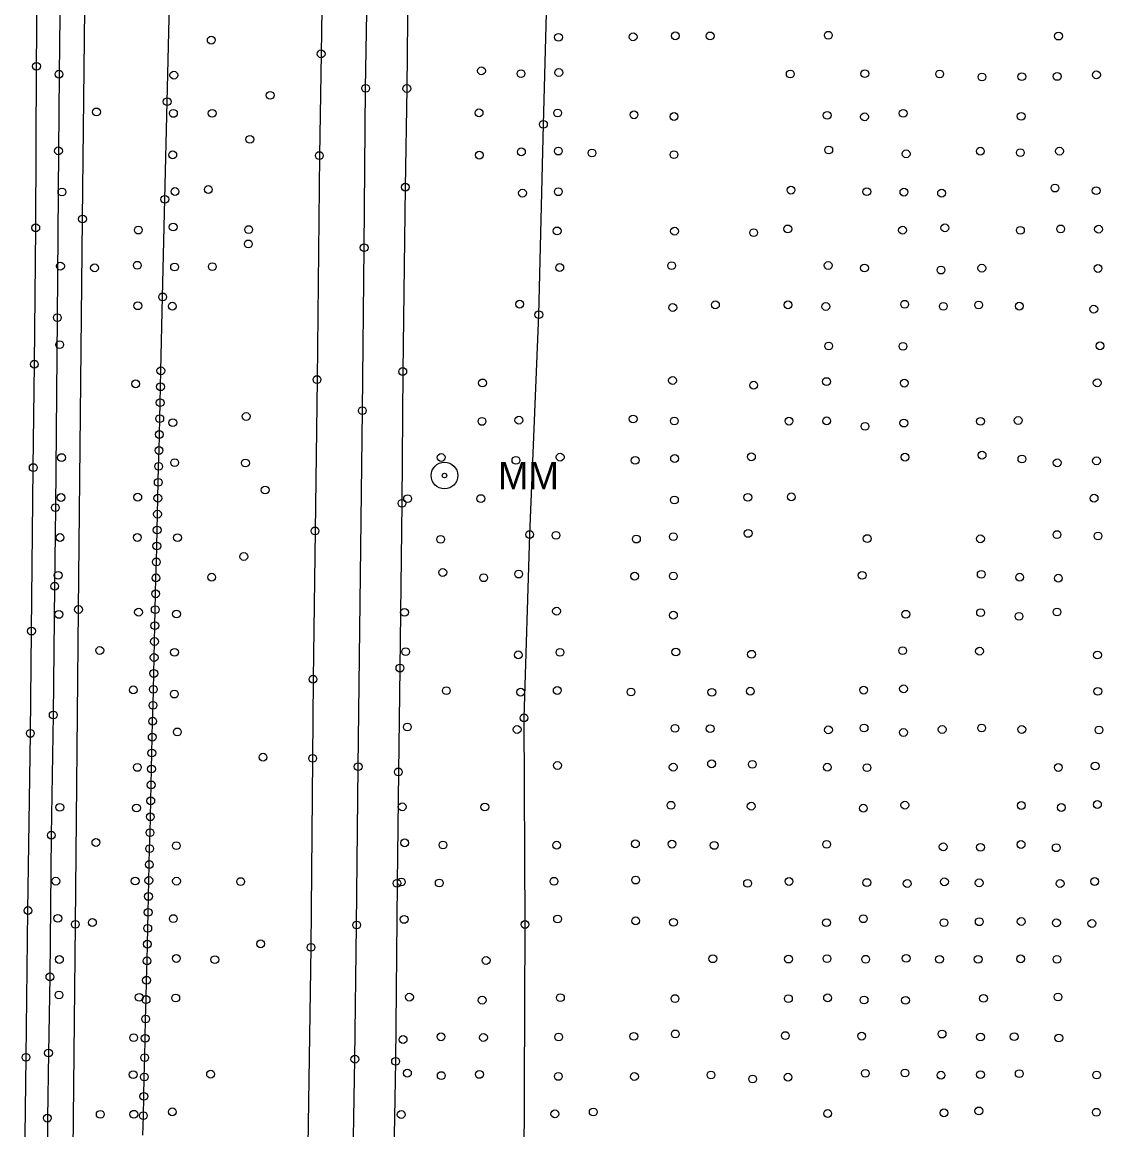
# Model space of a CAD drawing. Extents: x 20503438 to 20508873, y 7964251 to 7984667.
# Drawn here: x 20506609.5 to 20506886.4, y 7967934.6 to 7968218.3 of the extents above; entities that cross this region are included whole.
import ezdxf

# ---------------------------------------------------------------- set-up
doc = ezdxf.new("R2010")
doc.units = 0
for name, color, linetype in [('SurBreakLine', 7, 'Continuous'), ('SurConcreteSlab', 7, 'Continuous'), ('SurDrainageArrowDown', 7, 'Continuous'), ('SurDrainageArrowUp', 7, 'Continuous'), ('SurEdgeRoadPaved', 7, 'Continuous'), ('SurEdgeShoulderPaved', 7, 'Continuous'), ('SurGuardRailCable', 7, 'Continuous'), ('SurPointsNonDTM', 7, 'Continuous'), ('SurRoadPoints', 7, 'Continuous'), ('SurSurveyPoints', 7, 'Continuous')]:
    doc.layers.add(name, color=color, linetype=linetype)

msp = doc.modelspace()

# ---------------------------------------------------------------- linework, layer by layer
at = {"layer": 'SurBreakLine'}
msp.add_lwpolyline([(20506690.26, 7968518.48), (20506689.75, 7968484.33), (20506689.14, 7968441.26), (20506688.76, 7968414.99), (20506687.98, 7968360.62), (20506687.56, 7968335.59), (20506687.22, 7968303.54), (20506686.72, 7968264.08), (20506686.24, 7968221.64), (20506686.02, 7968210.16), (20506685.58, 7968184.12), (20506684.98, 7968126.76), (20506684.47, 7968088.01), (20506683.95, 7968050.04), (20506683.85, 7968029.76), (20506683.42, 7967981.38), (20506682.3, 7967907.93)], dxfattribs=at)
at = {"layer": 'SurConcreteSlab'}
msp.add_lwpolyline([(20506712.33, 7968509.69), (20506711.9, 7968484.13), (20506711.28, 7968449.91), (20506710.98, 7968435.8), (20506710.8, 7968427.34), (20506710.57, 7968413.18), (20506710.2, 7968376.16), (20506709.68, 7968335.8), (20506709.4, 7968315.24), (20506709.29, 7968306.55), (20506709.24, 7968300.91), (20506708.97, 7968272.73), (20506708.28, 7968236.62), (20506707.97, 7968201.29), (20506707.58, 7968176.03), (20506706.92, 7968128.82), (20506706.72, 7968095.09), (20506706.2, 7968052.89), (20506705.8, 7968026.3), (20506705.46, 7967997.77), (20506705.09, 7967952.19), (20506704.42, 7967914.18)], dxfattribs=at)
at = {"layer": 'SurDrainageArrowDown'}
msp.add_lwpolyline([(20506640.39, 7967933.31), (20506640.5, 7967938.27), (20506640.62, 7967943.22), (20506640.74, 7967948.18), (20506640.85, 7967953.13), (20506640.97, 7967958.09), (20506641.09, 7967963.04), (20506641.2, 7967968), (20506641.32, 7967972.95), (20506641.44, 7967977.91), (20506641.54, 7967982.19), (20506641.63, 7967986.26), (20506641.73, 7967990.34), (20506641.82, 7967994.42), (20506641.92, 7967998.5), (20506642.02, 7968002.58), (20506642.11, 7968006.66), (20506642.21, 7968010.73), (20506642.3, 7968014.81), (20506642.4, 7968018.89), (20506642.5, 7968022.97), (20506642.59, 7968027.05), (20506642.69, 7968031.13), (20506642.78, 7968035.21), (20506642.88, 7968039.28), (20506642.98, 7968043.36), (20506643.07, 7968047.44), (20506643.17, 7968051.52), (20506643.26, 7968055.6), (20506643.36, 7968059.68), (20506643.46, 7968063.76), (20506643.55, 7968067.83), (20506643.65, 7968071.91), (20506643.74, 7968075.99), (20506643.84, 7968080.07), (20506643.94, 7968084.15), (20506644.03, 7968088.23), (20506644.13, 7968092.3), (20506644.22, 7968096.38), (20506644.32, 7968100.46), (20506644.42, 7968104.54), (20506644.51, 7968108.62), (20506644.61, 7968112.7), (20506644.7, 7968116.77), (20506644.8, 7968120.85), (20506644.9, 7968124.93), (20506644.99, 7968129.01), (20506645.44, 7968147.93), (20506646.02, 7968172.92), (20506646.61, 7968197.92), (20506647.2, 7968222.91)], dxfattribs=at)
at = {"layer": 'SurDrainageArrowUp'}
msp.add_lwpolyline([(20506738, 7967924.5), (20506738.23, 7967987.24), (20506737.97, 7968040.14), (20506739.42, 7968087.08), (20506741.75, 7968143.37), (20506742.94, 7968192.11), (20506744.24, 7968239.72), (20506747.37, 7968292.34), (20506747.64, 7968338.63), (20506748.32, 7968361.98), (20506749.44, 7968389.93), (20506749.76, 7968438.94), (20506751.33, 7968487.3), (20506751.06, 7968489.97)], dxfattribs=at)
at = {"layer": 'SurEdgeRoadPaved'}
for points in [[(20506610.04, 7967919.68), (20506610.47, 7967953.23), (20506610.95, 7967990.8), (20506611.57, 7968036.16), (20506611.86, 7968062.36), (20506612.31, 7968104.23), (20506612.6, 7968130.7), (20506612.95, 7968165.62), (20506613.14, 7968206.99), (20506613.43, 7968233.98), (20506614.06, 7968276.04), (20506614.62, 7968307.91), (20506615.76, 7968378.52), (20506616.8, 7968454.85), (20506618.19, 7968552.78)], [(20506686.56, 7967334.59), (20506686.95, 7967373.78), (20506689.55, 7967556.46), (20506690.33, 7967629.33), (20506692, 7967750.22), (20506692.37, 7967781.34), (20506692.82, 7967818.08), (20506693.38, 7967854.94), (20506693.74, 7967887.88), (20506694.06, 7967917.79), (20506694.67, 7967952.73), (20506695.11, 7967987.1), (20506695.52, 7968027.63), (20506696.58, 7968118.81), (20506697.03, 7968160.54), (20506697.41, 7968201.34), (20506698.01, 7968235.32), (20506698.41, 7968270.98), (20506698.89, 7968306.65), (20506699.7, 7968354.59), (20506700.7, 7968438.24), (20506701.3, 7968479.04), (20506702.09, 7968524.73)]]:
    msp.add_lwpolyline(points, dxfattribs=at)
at = {"layer": 'SurEdgeShoulderPaved'}
msp.add_lwpolyline([(20506624.07, 7968571.84), (20506622.9, 7968477.89), (20506622.6, 7968440.86), (20506622.03, 7968407.41), (20506621.73, 7968387.9), (20506620.89, 7968340.34), (20506620.58, 7968323), (20506620.12, 7968296.25), (20506619.36, 7968242.53), (20506618.92, 7968204.96), (20506618.76, 7968185.33), (20506618.47, 7968142.62), (20506617.98, 7968093.95), (20506617.79, 7968073.85), (20506617.43, 7968040.86), (20506616.93, 7968010.09), (20506616.58, 7967973.81), (20506616.23, 7967954.34), (20506615.93, 7967937.65), (20506615.89, 7967920.93)], dxfattribs=at)
at = {"layer": 'SurGuardRailCable'}
msp.add_lwpolyline([(20506615.02, 7967359.71), (20506615.99, 7967430.36), (20506617.34, 7967530.35), (20506618.65, 7967630.34), (20506619.88, 7967727.43), (20506620.83, 7967791.42), (20506621.77, 7967855.41), (20506622.47, 7967921.12), (20506623.1, 7967987.28), (20506623.9, 7968067.87), (20506624.93, 7968167.87), (20506626.04, 7968267.86), (20506627.42, 7968367.85), (20506628.76, 7968467.84), (20506630.09, 7968567.83)], dxfattribs=at)
at = {"layer": 'SurPointsNonDTM'}
for centre in [(20506624.93, 7968167.87), (20506623.9, 7968067.87), (20506623.1, 7967987.28)]:
    msp.add_circle(centre, 1, dxfattribs=at)
at = {"layer": 'SurRoadPoints'}
for radius in [3.43, 0.571]:
    msp.add_circle((20506717.61, 7968102.19), radius, dxfattribs=at)
at = {"layer": 'SurSurveyPoints'}
for centre in [(20506657.89, 7968213.69), (20506746.81, 7968214.41), (20506765.91, 7968214.51), (20506776.71, 7968214.78), (20506785.62, 7968214.76), (20506815.89, 7968214.93), (20506874.83, 7968214.72), (20506686.02, 7968210.16), (20506613.14, 7968206.99), (20506618.92, 7968204.96), (20506648.32, 7968204.71), (20506727.08, 7968205.82), (20506737.21, 7968205.11), (20506746.89, 7968205.38), (20506806.14, 7968205), (20506825.23, 7968205.08), (20506844.39, 7968205.02), (20506855.23, 7968204.24), (20506865.43, 7968204.32), (20506874.49, 7968204.39), (20506884.55, 7968204.78), (20506697.41, 7968201.34), (20506707.97, 7968201.29), (20506672.96, 7968199.55), (20506646.61, 7968197.92), (20506628.5, 7968195.3), (20506648.2, 7968194.92), (20506658.12, 7968194.95), (20506726.47, 7968195.06), (20506746.58, 7968195.04), (20506766.15, 7968194.57), (20506776.38, 7968194.13), (20506815.61, 7968194.43), (20506825.17, 7968194.04), (20506835.07, 7968194.94), (20506865.28, 7968194.18), (20506742.94, 7968192.11), (20506667.78, 7968188.28), (20506618.76, 7968185.33), (20506648.03, 7968184.3), (20506726.54, 7968184.23), (20506737.31, 7968185.07), (20506746.77, 7968185.27), (20506755.38, 7968184.77), (20506776.37, 7968184.37), (20506816, 7968185.55), (20506835.82, 7968184.57), (20506854.83, 7968185.24), (20506865.05, 7968184.88), (20506875.08, 7968185.25), (20506685.58, 7968184.12), (20506707.58, 7968176.03), (20506873.93, 7968175.8), (20506619.65, 7968174.8), (20506646.02, 7968172.92), (20506648.6, 7968174.91), (20506657.15, 7968175.42), (20506737.58, 7968174.51), (20506746.76, 7968174.86), (20506806.33, 7968175.27), (20506825.75, 7968174.89), (20506835.25, 7968174.77), (20506844.89, 7968174.5), (20506884.46, 7968175.13), (20506612.95, 7968165.62), (20506639.23, 7968165.04), (20506648.15, 7968165.83), (20506667.46, 7968165.17), (20506746.45, 7968164.83), (20506776.52, 7968164.76), (20506796.78, 7968164.38), (20506805.51, 7968165.34), (20506834.89, 7968165.01), (20506845.73, 7968165.61), (20506865.08, 7968164.99), (20506875.39, 7968165.34), (20506885.08, 7968165.27), (20506667.4, 7968161.5), (20506697.03, 7968160.54), (20506638.97, 7968156.04), (20506775.78, 7968155.92), (20506815.85, 7968155.99), (20506619.28, 7968155.8), (20506628, 7968155.37), (20506648.5, 7968155.59), (20506658.16, 7968155.68), (20506747.12, 7968155.45), (20506825.14, 7968155.35), (20506844.75, 7968154.8), (20506855.2, 7968155.29), (20506884.93, 7968155.22), (20506645.44, 7968147.93), (20506639.09, 7968145.67), (20506647.93, 7968145.55), (20506736.85, 7968146.07), (20506776.06, 7968145.21), (20506786.98, 7968145.89), (20506805.57, 7968145.9), (20506815.25, 7968145.47), (20506835.43, 7968146.05), (20506845.34, 7968145.51), (20506854.38, 7968145.87), (20506864.81, 7968145.56), (20506883.86, 7968144.81), (20506618.47, 7968142.62), (20506741.75, 7968143.37), (20506619.08, 7968135.71), (20506815.97, 7968135.37), (20506835.02, 7968135.28), (20506885.44, 7968135.4), (20506612.6, 7968130.7), (20506644.99, 7968129.01), (20506706.92, 7968128.82), (20506638.53, 7968125.67), (20506644.9, 7968124.93), (20506684.98, 7968126.76), (20506727.36, 7968125.91), (20506776.01, 7968126.53), (20506796.79, 7968125.32), (20506815.42, 7968126.25), (20506835.34, 7968125.86), (20506884.74, 7968125.92), (20506644.8, 7968120.85), (20506644.7, 7968116.77), (20506666.83, 7968117.32), (20506696.58, 7968118.81), (20506736.66, 7968116.36), (20506765.91, 7968116.67), (20506776.47, 7968116.14), (20506805.82, 7968116.13), (20506815.48, 7968116.19), (20506864.5, 7968116.29), (20506648.05, 7968115.74), (20506727.22, 7968116.05), (20506825.3, 7968114.79), (20506835.24, 7968115.62), (20506854.87, 7968116.06), (20506644.61, 7968112.7), (20506644.51, 7968108.62), (20506619.56, 7968106.79), (20506648.52, 7968105.49), (20506666.64, 7968105.4), (20506716.77, 7968106.82), (20506735.9, 7968106.08), (20506747.22, 7968106.9), (20506766.43, 7968106.08), (20506776.53, 7968106.55), (20506796.2, 7968106.99), (20506835.54, 7968106.9), (20506855.26, 7968107.41), (20506865.46, 7968106.42), (20506874.5, 7968105.45), (20506884.56, 7968105.95), (20506612.31, 7968104.23), (20506644.42, 7968104.54), (20506644.32, 7968100.46), (20506619.4, 7968096.57), (20506639.07, 7968096.65), (20506644.22, 7968096.38), (20506671.69, 7968098.49), (20506708.16, 7968096.28), (20506726.92, 7968096.29), (20506795.29, 7968096.6), (20506806.41, 7968096.72), (20506883.94, 7968096.39), (20506617.98, 7968093.95), (20506706.72, 7968095.09), (20506776.48, 7968095.92), (20506644.13, 7968092.3), (20506644.03, 7968088.23), (20506684.47, 7968088.01), (20506619.15, 7968086.31), (20506638.97, 7968086.34), (20506649.25, 7968086.29), (20506716.63, 7968085.87), (20506739.42, 7968087.08), (20506746.16, 7968086.88), (20506766.75, 7968085.92), (20506776.19, 7968086.54), (20506795.36, 7968087.37), (20506825.85, 7968086.05), (20506854.84, 7968086), (20506874.43, 7968087.07), (20506884.96, 7968086.71), (20506643.94, 7968084.15), (20506643.84, 7968080.07), (20506666.23, 7968081.45), (20506618.7, 7968076.65), (20506717.18, 7968077.38), (20506736.59, 7968076.96), (20506766.3, 7968076.42), (20506776.22, 7968076.45), (20506824.54, 7968076.62), (20506855.05, 7968076.9), (20506617.79, 7968073.85), (20506643.74, 7968075.99), (20506658, 7968076.15), (20506727.65, 7968076.02), (20506864.88, 7968076.15), (20506874.77, 7968075.9), (20506643.65, 7968071.91), (20506618.87, 7968066.63), (20506639.27, 7968067.2), (20506643.55, 7968067.83), (20506648.98, 7968066.72), (20506707.37, 7968067.15), (20506746.3, 7968067.46), (20506776.23, 7968066.43), (20506835.74, 7968066.67), (20506854.88, 7968067.07), (20506864.71, 7968066.15), (20506874.46, 7968067.26), (20506611.86, 7968062.36), (20506643.46, 7968063.76), (20506643.36, 7968059.68), (20506629.35, 7968057.4), (20506648.49, 7968056.93), (20506707.67, 7968057.1), (20506747.17, 7968056.92), (20506776.85, 7968056.99), (20506834.94, 7968057.33), (20506854.61, 7968057.21), (20506643.26, 7968055.6), (20506736.51, 7968056.27), (20506796.23, 7968056.43), (20506884.8, 7968056.22), (20506643.17, 7968051.52), (20506706.2, 7968052.89), (20506683.95, 7968050.04), (20506637.95, 7968047.31), (20506643.07, 7968047.44), (20506648.42, 7968046.23), (20506718.08, 7968047.12), (20506737.12, 7968046.72), (20506746.48, 7968047.16), (20506765.35, 7968046.77), (20506786.08, 7968046.69), (20506795.93, 7968046.97), (20506824.95, 7968047.24), (20506835.15, 7968047.58), (20506884.89, 7968046.95), (20506642.98, 7968043.36), (20506617.43, 7968040.86), (20506737.97, 7968040.14), (20506642.88, 7968039.28), (20506708.08, 7968037.8), (20506736.21, 7968037.16), (20506776.64, 7968037.45), (20506785.63, 7968037.39), (20506815.93, 7968037.07), (20506825.05, 7968037.56), (20506845.04, 7968037.16), (20506855.15, 7968037.54), (20506865.43, 7968037.17), (20506885.21, 7968037.04), (20506611.57, 7968036.16), (20506642.78, 7968035.21), (20506649.19, 7968036.54), (20506835.14, 7968036.4), (20506642.69, 7968031.13), (20506671.15, 7968030.07), (20506683.85, 7968029.76), (20506786, 7968028.37), (20506796.45, 7968028.25), (20506638.96, 7968027.45), (20506642.59, 7968027.05), (20506695.52, 7968027.63), (20506705.8, 7968026.3), (20506746.55, 7968027.96), (20506776.17, 7968027.52), (20506815.64, 7968027.51), (20506825.81, 7968027.4), (20506874.77, 7968027.44), (20506884.21, 7968027.8), (20506642.5, 7968022.97), (20506619.1, 7968017.22), (20506638.75, 7968017.06), (20506642.4, 7968018.89), (20506706.79, 7968017.36), (20506727.94, 7968017.33), (20506775.61, 7968017.76), (20506796.15, 7968017.52), (20506824.86, 7968017.01), (20506835.5, 7968017.78), (20506865.32, 7968017.7), (20506875.56, 7968017.19), (20506884.79, 7968017.96), (20506642.3, 7968014.81), (20506616.93, 7968010.09), (20506642.21, 7968010.73), (20506628.36, 7968008.24), (20506642.11, 7968006.66), (20506648.95, 7968007.4), (20506707.43, 7968008.14), (20506717.22, 7968007.6), (20506746.34, 7968007.53), (20506766.5, 7968007.88), (20506775.85, 7968007.81), (20506786.67, 7968007.48), (20506815.46, 7968007.74), (20506845.31, 7968007.13), (20506854.86, 7968006.99), (20506865.25, 7968007.71), (20506874.25, 7968006.88), (20506642.02, 7968002.58), (20506618.09, 7967998.34), (20506638.41, 7967998.35), (20506641.92, 7967998.5), (20506648.99, 7967998.32), (20506665.43, 7967998.22), (20506705.46, 7967997.77), (20506706.56, 7967998.11), (20506716.27, 7967997.87), (20506745.66, 7967998.3), (20506766.57, 7967998.6), (20506795.22, 7967997.76), (20506805.84, 7967998.25), (20506825.75, 7967997.96), (20506836.09, 7967997.72), (20506845.63, 7967998.17), (20506854.52, 7967997.88), (20506875.24, 7967997.72), (20506884.08, 7967998.24), (20506641.82, 7967994.42), (20506610.95, 7967990.8), (20506618.62, 7967988.8), (20506641.73, 7967990.34), (20506648.18, 7967988.74), (20506707.27, 7967988.53), (20506746.57, 7967988.65), (20506824.84, 7967988.7), (20506627.46, 7967987.73), (20506641.63, 7967986.26), (20506695.11, 7967987.1), (20506738.23, 7967987.24), (20506766.55, 7967988.16), (20506776.24, 7967987.79), (20506815.42, 7967987.71), (20506845.51, 7967987.71), (20506854.54, 7967987.93), (20506865.28, 7967987.99), (20506874.3, 7967987.64), (20506883.38, 7967987.49), (20506641.54, 7967982.19), (20506670.54, 7967982.28), (20506683.42, 7967981.38), (20506619.01, 7967978.27), (20506641.44, 7967977.91), (20506648.96, 7967978.53), (20506658.82, 7967978.23), (20506728.27, 7967978.02), (20506786.32, 7967978.46), (20506805.69, 7967978.37), (20506815.55, 7967978.49), (20506825.44, 7967978.33), (20506835.82, 7967978.56), (20506844.37, 7967978.31), (20506854.26, 7967978.31), (20506865.13, 7967978.44), (20506874.43, 7967978.32), (20506616.58, 7967973.81), (20506641.32, 7967972.95), (20506618.9, 7967969.19), (20506708.64, 7967968.63), (20506874.71, 7967968.67), (20506639.44, 7967968.58), (20506641.2, 7967968), (20506648.8, 7967968.4), (20506727.26, 7967967.84), (20506747.29, 7967968.49), (20506776.65, 7967968.26), (20506805.67, 7967968.24), (20506815.7, 7967968.44), (20506825.05, 7967967.9), (20506835.67, 7967967.81), (20506855.64, 7967968.31), (20506641.09, 7967963.04), (20506638.03, 7967958.24), (20506640.97, 7967958.09), (20506707.01, 7967957.77), (20506716.72, 7967958.47), (20506727.59, 7967958.29), (20506746.86, 7967958.42), (20506766.1, 7967958.58), (20506776.73, 7967959.21), (20506804.87, 7967958.78), (20506824.43, 7967958.64), (20506845.02, 7967959.17), (20506854.87, 7967958.42), (20506863.49, 7967958.52), (20506874.9, 7967958.18), (20506610.47, 7967953.23), (20506616.23, 7967954.34), (20506640.85, 7967953.13), (20506694.67, 7967952.73), (20506705.09, 7967952.19), (20506637.9, 7967948.79), (20506657.72, 7967948.89), (20506708.12, 7967949.16), (20506726.56, 7967948.84), (20506825.36, 7967949.12), (20506835.54, 7967949.22), (20506864.78, 7967949.03), (20506640.74, 7967948.18), (20506716.78, 7967948.54), (20506746.75, 7967948.33), (20506766.25, 7967948.29), (20506785.85, 7967948.69), (20506796.51, 7967947.65), (20506805.58, 7967948.13), (20506844.75, 7967948.63), (20506854.86, 7967948.78), (20506884.59, 7967948.69), (20506640.62, 7967943.22), (20506615.93, 7967937.65), (20506629.47, 7967938.62), (20506638.08, 7967938.64), (20506640.5, 7967938.27), (20506647.93, 7967939.25), (20506706.53, 7967938.57), (20506745.88, 7967938.74), (20506755.7, 7967939.22), (20506815.73, 7967938.82), (20506845.5, 7967939), (20506854.44, 7967939.49), (20506884.53, 7967939.15)]:
    msp.add_circle(centre, 1, dxfattribs=at)

# ---------------------------------------------------------------- texts
at = {"layer": 'SurRoadPoints'}
msp.add_text('MM', height=6.995, rotation=360, dxfattribs=at).set_placement((20506731.32, 7968098.69))

doc.saveas('drawing.dxf')
